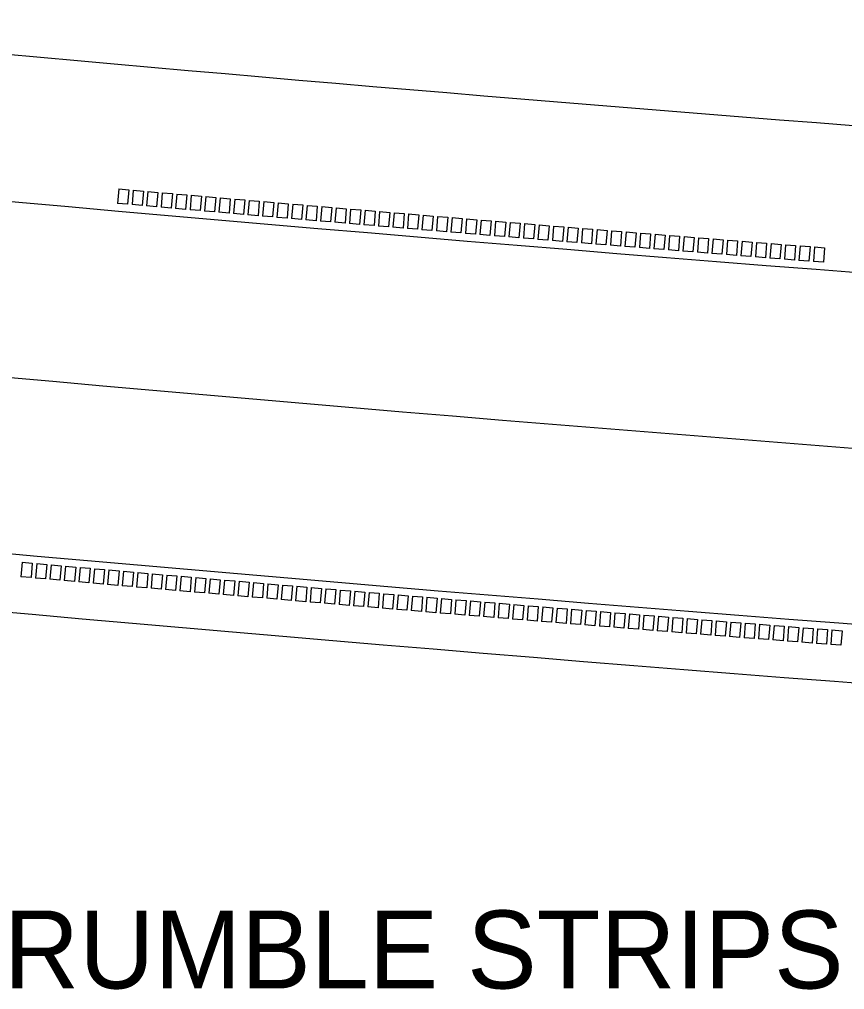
# Model space of a CAD drawing. Extents: x 49991.4 to 50021, y 49987.6 to 50011.4.
# Drawn here: x 50001.287 to 50001.923, y 49990.372 to 49991.118 of the extents above; entities that cross this region are included whole.
import ezdxf

# ---------------------------------------------------------------- set-up
doc = ezdxf.new("R2010")
doc.units = 0
doc.layers.add('Level 1', color=7, linetype='Continuous')
doc.layers.add('Level 2', color=7, linetype='Continuous')

msp = doc.modelspace()

# ---------------------------------------------------------------- linework, layer by layer
at = {"layer": 'Level 1'}
for p, q in [((50001.36378, 49990.98774), (50001.36279, 49990.97659)), ((50001.36378, 49990.98774), (50001.37155, 49990.98706)), ((50001.37155, 49990.98706), (50001.37056, 49990.9759)), ((50001.37494, 49990.98676), (50001.37395, 49990.9756)), ((50001.37494, 49990.98676), (50001.3827, 49990.98607)), ((50001.3827, 49990.98607), (50001.38171, 49990.97491)), ((50001.38609, 49990.98577), (50001.38511, 49990.97461)), ((50001.38609, 49990.98577), (50001.39386, 49990.98508)), ((50001.39386, 49990.98508), (50001.39287, 49990.97393)), ((50001.39725, 49990.98479), (50001.39626, 49990.97363)), ((50001.39725, 49990.98479), (50001.40501, 49990.9841)), ((50001.40501, 49990.9841), (50001.40403, 49990.97295)), ((50001.4084, 49990.9838), (50001.40742, 49990.97265)), ((50001.4084, 49990.9838), (50001.41617, 49990.98312)), ((50001.41617, 49990.98312), (50001.41519, 49990.97197)), ((50001.41956, 49990.98283), (50001.41858, 49990.97167)), ((50001.41956, 49990.98283), (50001.42732, 49990.98215)), ((50001.42732, 49990.98215), (50001.42634, 49990.97099)), ((50001.43071, 49990.98185), (50001.42974, 49990.97069)), ((50001.43071, 49990.98185), (50001.43848, 49990.98117)), ((50001.43848, 49990.98117), (50001.4375, 49990.97001)), ((50001.44187, 49990.98088), (50001.44089, 49990.96972)), ((50001.44187, 49990.98088), (50001.44963, 49990.9802)), ((50001.44963, 49990.9802), (50001.44866, 49990.96904)), ((50001.45302, 49990.9799), (50001.45205, 49990.96875)), ((50001.45302, 49990.9799), (50001.46079, 49990.97923)), ((50001.37056, 49990.9759), (50001.36279, 49990.97659)), ((50001.38171, 49990.97491), (50001.37395, 49990.9756)), ((50001.39287, 49990.97393), (50001.38511, 49990.97461)), ((50001.40403, 49990.97295), (50001.39626, 49990.97363)), ((50001.41519, 49990.97197), (50001.40742, 49990.97265)), ((50001.46079, 49990.97923), (50001.45982, 49990.96807)), ((50001.46418, 49990.97893), (50001.46321, 49990.96778)), ((50001.46418, 49990.97893), (50001.47195, 49990.97826)), ((50001.47195, 49990.97826), (50001.47098, 49990.9671)), ((50001.47534, 49990.97797), (50001.47437, 49990.96681)), ((50001.47534, 49990.97797), (50001.4831, 49990.9773)), ((50001.4831, 49990.9773), (50001.48214, 49990.96614)), ((50001.48649, 49990.977), (50001.48553, 49990.96584)), ((50001.48649, 49990.977), (50001.49426, 49990.97633)), ((50001.49426, 49990.97633), (50001.4933, 49990.96517)), ((50001.49765, 49990.97604), (50001.49669, 49990.96488)), ((50001.49765, 49990.97604), (50001.50542, 49990.97537)), ((50001.50542, 49990.97537), (50001.50446, 49990.96421)), ((50001.50881, 49990.97508), (50001.50785, 49990.96392)), ((50001.50881, 49990.97508), (50001.51657, 49990.97442)), ((50001.51657, 49990.97442), (50001.51562, 49990.96326)), ((50001.51996, 49990.97412), (50001.51901, 49990.96297)), ((50001.51996, 49990.97412), (50001.52773, 49990.97346)), ((50001.52773, 49990.97346), (50001.52678, 49990.9623)), ((50001.53112, 49990.97317), (50001.53017, 49990.96201)), ((50001.53112, 49990.97317), (50001.53889, 49990.97251)), ((50001.53889, 49990.97251), (50001.53794, 49990.96135)), ((50001.54228, 49990.97222), (50001.54133, 49990.96106)), ((50001.54228, 49990.97222), (50001.55005, 49990.97156)), ((50001.42634, 49990.97099), (50001.41858, 49990.97167)), ((50001.4375, 49990.97001), (50001.42974, 49990.97069)), ((50001.44866, 49990.96904), (50001.44089, 49990.96972)), ((50001.45982, 49990.96807), (50001.45205, 49990.96875)), ((50001.47098, 49990.9671), (50001.46321, 49990.96778)), ((50001.48214, 49990.96614), (50001.47437, 49990.96681)), ((50001.4933, 49990.96517), (50001.48553, 49990.96584)), ((50001.50446, 49990.96421), (50001.49669, 49990.96488)), ((50001.55005, 49990.97156), (50001.5491, 49990.9604)), ((50001.55344, 49990.97127), (50001.55249, 49990.96011)), ((50001.55344, 49990.97127), (50001.5612, 49990.97061)), ((50001.5612, 49990.97061), (50001.56026, 49990.95945)), ((50001.5646, 49990.97032), (50001.56365, 49990.95916)), ((50001.5646, 49990.97032), (50001.57236, 49990.96966)), ((50001.57236, 49990.96966), (50001.57142, 49990.9585)), ((50001.57575, 49990.96938), (50001.57481, 49990.95822)), ((50001.57575, 49990.96938), (50001.58352, 49990.96872)), ((50001.58352, 49990.96872), (50001.58258, 49990.95756)), ((50001.58691, 49990.96843), (50001.58597, 49990.95727)), ((50001.58691, 49990.96843), (50001.59468, 49990.96778)), ((50001.59468, 49990.96778), (50001.59374, 49990.95662)), ((50001.59807, 49990.96749), (50001.59713, 49990.95633)), ((50001.59807, 49990.96749), (50001.60584, 49990.96684)), ((50001.60584, 49990.96684), (50001.6049, 49990.95568)), ((50001.60923, 49990.96656), (50001.60829, 49990.95539)), ((50001.60923, 49990.96656), (50001.617, 49990.9659)), ((50001.617, 49990.9659), (50001.61606, 49990.95474)), ((50001.62039, 49990.96562), (50001.61945, 49990.95446)), ((50001.62039, 49990.96562), (50001.62816, 49990.96497)), ((50001.62816, 49990.96497), (50001.62722, 49990.95381)), ((50001.63155, 49990.96469), (50001.63062, 49990.95353)), ((50001.63155, 49990.96469), (50001.63932, 49990.96404)), ((50001.51562, 49990.96326), (50001.50785, 49990.96392)), ((50001.52678, 49990.9623), (50001.51901, 49990.96297)), ((50001.53794, 49990.96135), (50001.53017, 49990.96201)), ((50001.5491, 49990.9604), (50001.54133, 49990.96106)), ((50001.56026, 49990.95945), (50001.55249, 49990.96011)), ((50001.57142, 49990.9585), (50001.56365, 49990.95916)), ((50001.58258, 49990.95756), (50001.57481, 49990.95822)), ((50001.59374, 49990.95662), (50001.58597, 49990.95727)), ((50001.63932, 49990.96404), (50001.63838, 49990.95288)), ((50001.64271, 49990.96376), (50001.64178, 49990.9526)), ((50001.64271, 49990.96376), (50001.65047, 49990.96311)), ((50001.65047, 49990.96311), (50001.64955, 49990.95195)), ((50001.65387, 49990.96283), (50001.65294, 49990.95167)), ((50001.65387, 49990.96283), (50001.66163, 49990.96219)), ((50001.66163, 49990.96219), (50001.66071, 49990.95102)), ((50001.66503, 49990.9619), (50001.6641, 49990.95074)), ((50001.66503, 49990.9619), (50001.67279, 49990.96126)), ((50001.67279, 49990.96126), (50001.67187, 49990.9501)), ((50001.67619, 49990.96098), (50001.67526, 49990.94982)), ((50001.67619, 49990.96098), (50001.68395, 49990.96034)), ((50001.68395, 49990.96034), (50001.68303, 49990.94918)), ((50001.68735, 49990.96006), (50001.68643, 49990.9489)), ((50001.68735, 49990.96006), (50001.69512, 49990.95942)), ((50001.69512, 49990.95942), (50001.6942, 49990.94826)), ((50001.69851, 49990.95914), (50001.69759, 49990.94798)), ((50001.69851, 49990.95914), (50001.70628, 49990.95851)), ((50001.70628, 49990.95851), (50001.70536, 49990.94734)), ((50001.70967, 49990.95823), (50001.70875, 49990.94706)), ((50001.70967, 49990.95823), (50001.71744, 49990.95759)), ((50001.71744, 49990.95759), (50001.71652, 49990.94643)), ((50001.72083, 49990.95731), (50001.71992, 49990.94615)), ((50001.72083, 49990.95731), (50001.7286, 49990.95668)), ((50001.6049, 49990.95568), (50001.59713, 49990.95633)), ((50001.61606, 49990.95474), (50001.60829, 49990.95539)), ((50001.62722, 49990.95381), (50001.61945, 49990.95446)), ((50001.63838, 49990.95288), (50001.63062, 49990.95353)), ((50001.64955, 49990.95195), (50001.64178, 49990.9526)), ((50001.66071, 49990.95102), (50001.65294, 49990.95167)), ((50001.67187, 49990.9501), (50001.6641, 49990.95074)), ((50001.68303, 49990.94918), (50001.67526, 49990.94982)), ((50001.7286, 49990.95668), (50001.72769, 49990.94552)), ((50001.73199, 49990.9564), (50001.73108, 49990.94524)), ((50001.73199, 49990.9564), (50001.73976, 49990.95577)), ((50001.73976, 49990.95577), (50001.73885, 49990.94461)), ((50001.74315, 49990.95549), (50001.74224, 49990.94433)), ((50001.74315, 49990.95549), (50001.75092, 49990.95486)), ((50001.75092, 49990.95486), (50001.75001, 49990.9437)), ((50001.75431, 49990.95459), (50001.75341, 49990.94343)), ((50001.75431, 49990.95459), (50001.76208, 49990.95396)), ((50001.76208, 49990.95396), (50001.76118, 49990.9428)), ((50001.76547, 49990.95369), (50001.76457, 49990.94252)), ((50001.76547, 49990.95369), (50001.77324, 49990.95306)), ((50001.77324, 49990.95306), (50001.77234, 49990.94189)), ((50001.77664, 49990.95278), (50001.77574, 49990.94162)), ((50001.77664, 49990.95278), (50001.78441, 49990.95216)), ((50001.78441, 49990.95216), (50001.78351, 49990.94099)), ((50001.7878, 49990.95189), (50001.7869, 49990.94072)), ((50001.7878, 49990.95189), (50001.79557, 49990.95126)), ((50001.79557, 49990.95126), (50001.79467, 49990.9401)), ((50001.79896, 49990.95099), (50001.79807, 49990.93983)), ((50001.79896, 49990.95099), (50001.80673, 49990.95037)), ((50001.80673, 49990.95037), (50001.80584, 49990.9392)), ((50001.81012, 49990.9501), (50001.80923, 49990.93893)), ((50001.81012, 49990.9501), (50001.81789, 49990.94947)), ((50001.6942, 49990.94826), (50001.68643, 49990.9489)), ((50001.70536, 49990.94734), (50001.69759, 49990.94798)), ((50001.71652, 49990.94643), (50001.70875, 49990.94706)), ((50001.72769, 49990.94552), (50001.71992, 49990.94615)), ((50001.73885, 49990.94461), (50001.73108, 49990.94524)), ((50001.75001, 49990.9437), (50001.74224, 49990.94433)), ((50001.76118, 49990.9428), (50001.75341, 49990.94343)), ((50001.77234, 49990.94189), (50001.76457, 49990.94252)), ((50001.81789, 49990.94947), (50001.817, 49990.93831)), ((50001.82129, 49990.9492), (50001.8204, 49990.93804)), ((50001.82129, 49990.9492), (50001.82906, 49990.94859)), ((50001.82906, 49990.94859), (50001.82817, 49990.93742)), ((50001.83245, 49990.94832), (50001.83156, 49990.93715)), ((50001.83245, 49990.94832), (50001.84022, 49990.9477)), ((50001.84022, 49990.9477), (50001.83933, 49990.93653)), ((50001.84361, 49990.94743), (50001.84273, 49990.93626)), ((50001.84361, 49990.94743), (50001.85138, 49990.94681)), ((50001.85138, 49990.94681), (50001.8505, 49990.93565)), ((50001.85478, 49990.94654), (50001.85389, 49990.93538)), ((50001.85478, 49990.94654), (50001.86255, 49990.94593)), ((50001.86255, 49990.94593), (50001.86166, 49990.93477)), ((50001.86594, 49990.94566), (50001.86506, 49990.9345)), ((50001.86594, 49990.94566), (50001.87371, 49990.94505)), ((50001.87371, 49990.94505), (50001.87283, 49990.93389)), ((50001.8771, 49990.94478), (50001.87622, 49990.93362)), ((50001.8771, 49990.94478), (50001.88487, 49990.94417)), ((50001.88487, 49990.94417), (50001.884, 49990.93301)), ((50001.88827, 49990.94391), (50001.88739, 49990.93274)), ((50001.88827, 49990.94391), (50001.89604, 49990.9433)), ((50001.89604, 49990.9433), (50001.89516, 49990.93213)), ((50001.89943, 49990.94303), (50001.89856, 49990.93187)), ((50001.89943, 49990.94303), (50001.9072, 49990.94243)), ((50001.9072, 49990.94243), (50001.90633, 49990.93126)), ((50001.78351, 49990.94099), (50001.77574, 49990.94162)), ((50001.79467, 49990.9401), (50001.7869, 49990.94072)), ((50001.80584, 49990.9392), (50001.79807, 49990.93983)), ((50001.817, 49990.93831), (50001.80923, 49990.93893)), ((50001.82817, 49990.93742), (50001.8204, 49990.93804)), ((50001.83933, 49990.93653), (50001.83156, 49990.93715)), ((50001.8505, 49990.93565), (50001.84273, 49990.93626)), ((50001.86166, 49990.93477), (50001.85389, 49990.93538)), ((50001.87283, 49990.93389), (50001.86506, 49990.9345)), ((50001.884, 49990.93301), (50001.87622, 49990.93362)), ((50001.89516, 49990.93213), (50001.88739, 49990.93274)), ((50001.90633, 49990.93126), (50001.89856, 49990.93187)), ((50001.2894, 49990.70043), (50001.2884, 49990.68927)), ((50001.2894, 49990.70043), (50001.29717, 49990.69972)), ((50001.29717, 49990.69972), (50001.29617, 49990.68858)), ((50001.30053, 49990.69943), (50001.29953, 49990.68828)), ((50001.30053, 49990.69943), (50001.3083, 49990.69873)), ((50001.3083, 49990.69873), (50001.3073, 49990.68758)), ((50001.31166, 49990.69844), (50001.31066, 49990.68728)), ((50001.31166, 49990.69844), (50001.31943, 49990.69773)), ((50001.31943, 49990.69773), (50001.31843, 49990.68659)), ((50001.32279, 49990.69744), (50001.32179, 49990.68629)), ((50001.32279, 49990.69744), (50001.33055, 49990.69674)), ((50001.33055, 49990.69674), (50001.32956, 49990.6856)), ((50001.33391, 49990.69645), (50001.33292, 49990.6853)), ((50001.33391, 49990.69645), (50001.34168, 49990.69576)), ((50001.29617, 49990.68858), (50001.2884, 49990.68927)), ((50001.34168, 49990.69576), (50001.34069, 49990.68461)), ((50001.34504, 49990.69547), (50001.34405, 49990.68431)), ((50001.34504, 49990.69547), (50001.35281, 49990.69477)), ((50001.35281, 49990.69477), (50001.35182, 49990.68362)), ((50001.35617, 49990.69448), (50001.35518, 49990.68333)), ((50001.35617, 49990.69448), (50001.36394, 49990.69379)), ((50001.36394, 49990.69379), (50001.36296, 49990.68264)), ((50001.3673, 49990.6935), (50001.36632, 49990.68234)), ((50001.3673, 49990.6935), (50001.37507, 49990.69281)), ((50001.37507, 49990.69281), (50001.37409, 49990.68166)), ((50001.37843, 49990.69252), (50001.37745, 49990.68136)), ((50001.37843, 49990.69252), (50001.3862, 49990.69183)), ((50001.3862, 49990.69183), (50001.38522, 49990.68068)), ((50001.38956, 49990.69154), (50001.38858, 49990.68039)), ((50001.38956, 49990.69154), (50001.39733, 49990.69085)), ((50001.39733, 49990.69085), (50001.39635, 49990.6797)), ((50001.40069, 49990.69057), (50001.39971, 49990.67941)), ((50001.40069, 49990.69057), (50001.40846, 49990.68988)), ((50001.40846, 49990.68988), (50001.40748, 49990.67873)), ((50001.41182, 49990.68959), (50001.41084, 49990.67844)), ((50001.41182, 49990.68959), (50001.41959, 49990.68891)), ((50001.41959, 49990.68891), (50001.41861, 49990.67776)), ((50001.42295, 49990.68862), (50001.42197, 49990.67747)), ((50001.42295, 49990.68862), (50001.43072, 49990.68794)), ((50001.3073, 49990.68758), (50001.29953, 49990.68828)), ((50001.31843, 49990.68659), (50001.31066, 49990.68728)), ((50001.32956, 49990.6856), (50001.32179, 49990.68629)), ((50001.34069, 49990.68461), (50001.33292, 49990.6853)), ((50001.35182, 49990.68362), (50001.34405, 49990.68431)), ((50001.36296, 49990.68264), (50001.35518, 49990.68333)), ((50001.37409, 49990.68166), (50001.36632, 49990.68234)), ((50001.38522, 49990.68068), (50001.37745, 49990.68136)), ((50001.43072, 49990.68794), (50001.42975, 49990.67679)), ((50001.43408, 49990.68766), (50001.43311, 49990.6765)), ((50001.43408, 49990.68766), (50001.44185, 49990.68697)), ((50001.44185, 49990.68697), (50001.44088, 49990.67582)), ((50001.44521, 49990.68669), (50001.44424, 49990.67553)), ((50001.44521, 49990.68669), (50001.45298, 49990.68601)), ((50001.45298, 49990.68601), (50001.45201, 49990.67486)), ((50001.45634, 49990.68573), (50001.45537, 49990.67457)), ((50001.45634, 49990.68573), (50001.46411, 49990.68505)), ((50001.46411, 49990.68505), (50001.46314, 49990.6739)), ((50001.46747, 49990.68477), (50001.4665, 49990.67361)), ((50001.46747, 49990.68477), (50001.47524, 49990.68409)), ((50001.47524, 49990.68409), (50001.47428, 49990.67294)), ((50001.4786, 49990.68381), (50001.47764, 49990.67265)), ((50001.4786, 49990.68381), (50001.48637, 49990.68313)), ((50001.48637, 49990.68313), (50001.48541, 49990.67198)), ((50001.48973, 49990.68285), (50001.48877, 49990.67169)), ((50001.48973, 49990.68285), (50001.4975, 49990.68218)), ((50001.4975, 49990.68218), (50001.49654, 49990.67103)), ((50001.50086, 49990.6819), (50001.49991, 49990.67074)), ((50001.50086, 49990.6819), (50001.50863, 49990.68123)), ((50001.50863, 49990.68123), (50001.50768, 49990.67007)), ((50001.51199, 49990.68095), (50001.51104, 49990.66979)), ((50001.51199, 49990.68095), (50001.51976, 49990.68028)), ((50001.39635, 49990.6797), (50001.38858, 49990.68039)), ((50001.40748, 49990.67873), (50001.39971, 49990.67941)), ((50001.41861, 49990.67776), (50001.41084, 49990.67844)), ((50001.42975, 49990.67679), (50001.42197, 49990.67747)), ((50001.44088, 49990.67582), (50001.43311, 49990.6765)), ((50001.45201, 49990.67486), (50001.44424, 49990.67553)), ((50001.46314, 49990.6739), (50001.45537, 49990.67457)), ((50001.47428, 49990.67294), (50001.4665, 49990.67361)), ((50001.51976, 49990.68028), (50001.51881, 49990.66913)), ((50001.52312, 49990.68), (50001.52217, 49990.66884)), ((50001.52312, 49990.68), (50001.53089, 49990.67933)), ((50001.53089, 49990.67933), (50001.52995, 49990.66818)), ((50001.53425, 49990.67905), (50001.53331, 49990.66789)), ((50001.53425, 49990.67905), (50001.54203, 49990.67838)), ((50001.54203, 49990.67838), (50001.54108, 49990.66723)), ((50001.54539, 49990.67811), (50001.54444, 49990.66695)), ((50001.54539, 49990.67811), (50001.55316, 49990.67744)), ((50001.55316, 49990.67744), (50001.55222, 49990.66629)), ((50001.55652, 49990.67717), (50001.55558, 49990.66601)), ((50001.55652, 49990.67717), (50001.56429, 49990.6765)), ((50001.56429, 49990.6765), (50001.56335, 49990.66535)), ((50001.56765, 49990.67623), (50001.56671, 49990.66507)), ((50001.56765, 49990.67623), (50001.57542, 49990.67557)), ((50001.57542, 49990.67557), (50001.57449, 49990.66441)), ((50001.57878, 49990.67529), (50001.57785, 49990.66413)), ((50001.57878, 49990.67529), (50001.58656, 49990.67463)), ((50001.58656, 49990.67463), (50001.58562, 49990.66348)), ((50001.58992, 49990.67436), (50001.58898, 49990.6632)), ((50001.58992, 49990.67436), (50001.59769, 49990.6737)), ((50001.59769, 49990.6737), (50001.59676, 49990.66255)), ((50001.60105, 49990.67343), (50001.60012, 49990.66226)), ((50001.60105, 49990.67343), (50001.60882, 49990.67277)), ((50001.48541, 49990.67198), (50001.47764, 49990.67265)), ((50001.49654, 49990.67103), (50001.48877, 49990.67169)), ((50001.50768, 49990.67007), (50001.49991, 49990.67074)), ((50001.51881, 49990.66913), (50001.51104, 49990.66979)), ((50001.52995, 49990.66818), (50001.52217, 49990.66884)), ((50001.54108, 49990.66723), (50001.53331, 49990.66789)), ((50001.55222, 49990.66629), (50001.54444, 49990.66695)), ((50001.56335, 49990.66535), (50001.55558, 49990.66601)), ((50001.60882, 49990.67277), (50001.60789, 49990.66161)), ((50001.61218, 49990.6725), (50001.61125, 49990.66133)), ((50001.61218, 49990.6725), (50001.61996, 49990.67184)), ((50001.61996, 49990.67184), (50001.61903, 49990.66069)), ((50001.62332, 49990.67157), (50001.62239, 49990.66041)), ((50001.62332, 49990.67157), (50001.63109, 49990.67091)), ((50001.63109, 49990.67091), (50001.63016, 49990.65976)), ((50001.63445, 49990.67064), (50001.63352, 49990.65948)), ((50001.63445, 49990.67064), (50001.64222, 49990.66999)), ((50001.64222, 49990.66999), (50001.6413, 49990.65884)), ((50001.64558, 49990.66972), (50001.64466, 49990.65856)), ((50001.64558, 49990.66972), (50001.65336, 49990.66907)), ((50001.65336, 49990.66907), (50001.65244, 49990.65792)), ((50001.65672, 49990.6688), (50001.6558, 49990.65764)), ((50001.65672, 49990.6688), (50001.66449, 49990.66815)), ((50001.66449, 49990.66815), (50001.66357, 49990.657)), ((50001.66785, 49990.66788), (50001.66693, 49990.65672)), ((50001.66785, 49990.66788), (50001.67563, 49990.66724)), ((50001.67563, 49990.66724), (50001.67471, 49990.65608)), ((50001.67899, 49990.66697), (50001.67807, 49990.65581)), ((50001.67899, 49990.66697), (50001.68676, 49990.66632)), ((50001.68676, 49990.66632), (50001.68585, 49990.65517)), ((50001.69012, 49990.66606), (50001.68921, 49990.65489)), ((50001.69012, 49990.66606), (50001.69789, 49990.66541)), ((50001.57449, 49990.66441), (50001.56671, 49990.66507)), ((50001.58562, 49990.66348), (50001.57785, 49990.66413)), ((50001.59676, 49990.66255), (50001.58898, 49990.6632)), ((50001.60789, 49990.66161), (50001.60012, 49990.66226)), ((50001.61903, 49990.66069), (50001.61125, 49990.66133)), ((50001.63016, 49990.65976), (50001.62239, 49990.66041)), ((50001.6413, 49990.65884), (50001.63352, 49990.65948)), ((50001.65244, 49990.65792), (50001.64466, 49990.65856)), ((50001.69789, 49990.66541), (50001.69698, 49990.65426)), ((50001.70126, 49990.66515), (50001.70035, 49990.65398)), ((50001.70126, 49990.66515), (50001.70903, 49990.6645)), ((50001.70903, 49990.6645), (50001.70812, 49990.65335)), ((50001.71239, 49990.66424), (50001.71148, 49990.65308)), ((50001.71239, 49990.66424), (50001.72016, 49990.6636)), ((50001.72016, 49990.6636), (50001.71926, 49990.65244)), ((50001.72353, 49990.66333), (50001.72262, 49990.65217)), ((50001.72353, 49990.66333), (50001.7313, 49990.66269)), ((50001.7313, 49990.66269), (50001.7304, 49990.65154)), ((50001.73466, 49990.66243), (50001.73376, 49990.65127)), ((50001.73466, 49990.66243), (50001.74244, 49990.66179)), ((50001.74244, 49990.66179), (50001.74153, 49990.65064)), ((50001.7458, 49990.66153), (50001.7449, 49990.65037)), ((50001.7458, 49990.66153), (50001.75357, 49990.66089)), ((50001.75357, 49990.66089), (50001.75267, 49990.64974)), ((50001.75693, 49990.66063), (50001.75603, 49990.64947)), ((50001.75693, 49990.66063), (50001.76471, 49990.66)), ((50001.76471, 49990.66), (50001.76381, 49990.64884)), ((50001.76807, 49990.65974), (50001.76717, 49990.64857)), ((50001.76807, 49990.65974), (50001.77584, 49990.6591)), ((50001.77584, 49990.6591), (50001.77495, 49990.64795)), ((50001.77921, 49990.65884), (50001.77831, 49990.64768)), ((50001.77921, 49990.65884), (50001.78698, 49990.65821)), ((50001.66357, 49990.657), (50001.6558, 49990.65764)), ((50001.67471, 49990.65608), (50001.66693, 49990.65672)), ((50001.68585, 49990.65517), (50001.67807, 49990.65581)), ((50001.69698, 49990.65426), (50001.68921, 49990.65489)), ((50001.70812, 49990.65335), (50001.70035, 49990.65398)), ((50001.71926, 49990.65244), (50001.71148, 49990.65308)), ((50001.7304, 49990.65154), (50001.72262, 49990.65217)), ((50001.74153, 49990.65064), (50001.73376, 49990.65127)), ((50001.78698, 49990.65821), (50001.78609, 49990.64706)), ((50001.79034, 49990.65795), (50001.78945, 49990.64679)), ((50001.79034, 49990.65795), (50001.79812, 49990.65732)), ((50001.79812, 49990.65732), (50001.79723, 49990.64617)), ((50001.80148, 49990.65706), (50001.80059, 49990.6459)), ((50001.80148, 49990.65706), (50001.80925, 49990.65644)), ((50001.80925, 49990.65644), (50001.80837, 49990.64528)), ((50001.81262, 49990.65618), (50001.81173, 49990.64501)), ((50001.81262, 49990.65618), (50001.82039, 49990.65555)), ((50001.82039, 49990.65555), (50001.81951, 49990.6444)), ((50001.82375, 49990.65529), (50001.82287, 49990.64413)), ((50001.82375, 49990.65529), (50001.83153, 49990.65467)), ((50001.83153, 49990.65467), (50001.83065, 49990.64351)), ((50001.83489, 49990.65441), (50001.83401, 49990.64325)), ((50001.83489, 49990.65441), (50001.84266, 49990.65379)), ((50001.84266, 49990.65379), (50001.84178, 49990.64263)), ((50001.84603, 49990.65353), (50001.84515, 49990.64237)), ((50001.84603, 49990.65353), (50001.8538, 49990.65291)), ((50001.8538, 49990.65291), (50001.85292, 49990.64176)), ((50001.85716, 49990.65266), (50001.85629, 49990.64149)), ((50001.85716, 49990.65266), (50001.86494, 49990.65204)), ((50001.86494, 49990.65204), (50001.86406, 49990.64088)), ((50001.8683, 49990.65178), (50001.86743, 49990.64062)), ((50001.8683, 49990.65178), (50001.87608, 49990.65117)), ((50001.87608, 49990.65117), (50001.87521, 49990.64001)), ((50001.75267, 49990.64974), (50001.7449, 49990.65037)), ((50001.76381, 49990.64884), (50001.75603, 49990.64947)), ((50001.77495, 49990.64795), (50001.76717, 49990.64857)), ((50001.78609, 49990.64706), (50001.77831, 49990.64768)), ((50001.79723, 49990.64617), (50001.78945, 49990.64679)), ((50001.80837, 49990.64528), (50001.80059, 49990.6459)), ((50001.81951, 49990.6444), (50001.81173, 49990.64501)), ((50001.83065, 49990.64351), (50001.82287, 49990.64413)), ((50001.87944, 49990.65091), (50001.87857, 49990.63975)), ((50001.87944, 49990.65091), (50001.88722, 49990.6503)), ((50001.88722, 49990.6503), (50001.88635, 49990.63914)), ((50001.89058, 49990.65004), (50001.88971, 49990.63888)), ((50001.89058, 49990.65004), (50001.89835, 49990.64943)), ((50001.89835, 49990.64943), (50001.89749, 49990.63827)), ((50001.90172, 49990.64918), (50001.90085, 49990.63801)), ((50001.90172, 49990.64918), (50001.90949, 49990.64856)), ((50001.90949, 49990.64856), (50001.90863, 49990.63741)), ((50001.91286, 49990.64831), (50001.91199, 49990.63715)), ((50001.91286, 49990.64831), (50001.92063, 49990.6477)), ((50001.92063, 49990.6477), (50001.91977, 49990.63654)), ((50001.84178, 49990.64263), (50001.83401, 49990.64325)), ((50001.85292, 49990.64176), (50001.84515, 49990.64237)), ((50001.86406, 49990.64088), (50001.85629, 49990.64149)), ((50001.87521, 49990.64001), (50001.86743, 49990.64062)), ((50001.88635, 49990.63914), (50001.87857, 49990.63975)), ((50001.89749, 49990.63827), (50001.88971, 49990.63888)), ((50001.90863, 49990.63741), (50001.90085, 49990.63801)), ((50001.91977, 49990.63654), (50001.91199, 49990.63715))]:
    msp.add_line(p, q, dxfattribs=at)
for radius, end in [(51.23325, 268.586561), (51.34575, 270), (51.48075, 270), (51.61575, 270), (51.66075, 270)]:
    msp.add_arc((50005.90121, 50042.11555), radius, 264.5, end, dxfattribs=at)

# ---------------------------------------------------------------- texts
at = {"layer": 'Level 2'}
msp.add_text('INTERMITTENT RUMBLE STRIPS', height=0.06, rotation=359.99995, dxfattribs=at).set_placement((50000.6647, 49990.3724))

doc.saveas('drawing.dxf')
